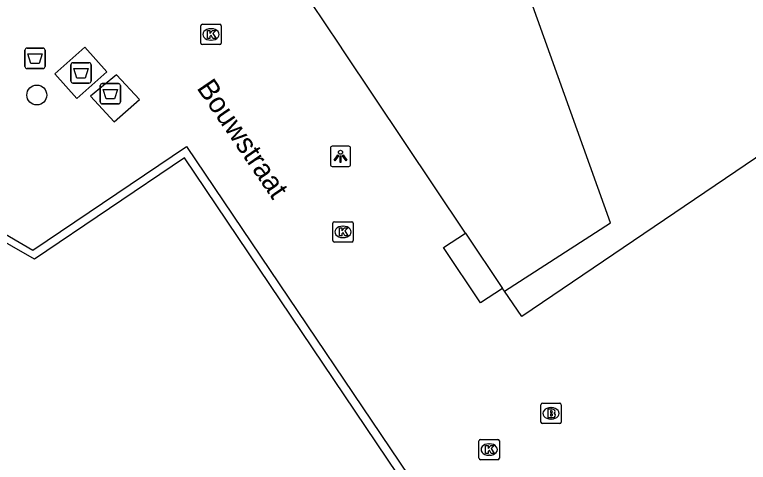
# Model space of a CAD drawing. Extents: x 161087 to 161922, y 382574 to 383873.
# Drawn here: x 161601.28 to 161637.33, y 382943.67 to 382965.65 of the extents above; entities that cross this region are included whole.
import ezdxf

# ---------------------------------------------------------------- set-up
doc = ezdxf.new("R2010")
doc.units = 0
for name, color, linetype in [('IMGEO_Afval_apart_plaats', 7, 'Continuous'), ('IMGEO_Afvalbak', 7, 'Continuous'), ('IMGEO_Boom', 7, 'Continuous'), ('IMGEO_Brandkraan', 7, 'Continuous'), ('IMGEO_Kolk', 7, 'Continuous'), ('IMGEO_Lichtpunt', 7, 'Continuous'), ('IMGEO_Openbare_ruimte_label', 7, 'Continuous'), ('IMGEO_Pand', 7, 'Continuous'), ('IMGEO_Voetpad_gesloten', 7, 'Continuous'), ('IMGEO_Voetpad_open', 7, 'Continuous')]:
    doc.layers.add(name, color=color, linetype=linetype)

msp = doc.modelspace()

# ---------------------------------------------------------------- linework, layer by layer
at = {"layer": 'IMGEO_Afval_apart_plaats'}
for p, q in [((161604.039, 382962.391), (161604.039, 382963.191)), ((161604.039, 382963.191), (161604.039, 382962.391)), ((161604.139, 382963.291), (161604.929, 382963.291)), ((161604.929, 382963.291), (161604.139, 382963.291)), ((161605.029, 382963.191), (161605.029, 382962.391)), ((161605.029, 382962.391), (161605.029, 382963.191)), ((161604.929, 382962.291), (161604.139, 382962.291)), ((161604.139, 382962.291), (161604.929, 382962.291)), ((161605.484, 382961.368), (161605.484, 382962.168)), ((161605.484, 382962.168), (161605.484, 382961.368)), ((161605.584, 382962.268), (161606.374, 382962.268)), ((161606.374, 382962.268), (161605.584, 382962.268)), ((161606.474, 382962.168), (161606.474, 382961.368)), ((161606.474, 382961.368), (161606.474, 382962.168)), ((161606.374, 382961.268), (161605.584, 382961.268)), ((161605.584, 382961.268), (161606.374, 382961.268))]:
    msp.add_line(p, q, dxfattribs=at)
for points in [[(161604.182, 382963.005), (161604.886, 382963.005), (161604.737, 382962.535), (161604.331, 382962.535), (161604.182, 382963.005)], [(161605.627, 382961.982), (161606.331, 382961.982), (161606.182, 382961.512), (161605.776, 382961.512), (161605.627, 382961.982)]]:
    msp.add_lwpolyline(points, dxfattribs=at)
for centre, start, end in [((161604.139, 382963.191), 90, 180), ((161604.139, 382963.191), 90, 180), ((161604.929, 382963.191), 0, 90), ((161604.929, 382963.191), 360, 90), ((161604.139, 382962.391), 180, 270), ((161604.139, 382962.391), 180, 270), ((161604.929, 382962.391), 270, 0), ((161604.929, 382962.391), 270, 0), ((161605.584, 382962.168), 90, 180), ((161605.584, 382962.168), 90, 180), ((161606.374, 382962.168), 0, 90), ((161606.374, 382962.168), 360, 90), ((161605.584, 382961.368), 180, 270), ((161605.584, 382961.368), 180, 270), ((161606.374, 382961.368), 270, 0), ((161606.374, 382961.368), 270, 0)]:
    msp.add_arc(centre, 0.1, start, end, dxfattribs=at)
at = {"layer": 'IMGEO_Afvalbak'}
for p, q in [((161601.784, 382963.106), (161601.784, 382963.906)), ((161601.784, 382963.906), (161601.784, 382963.106)), ((161601.884, 382964.006), (161602.674, 382964.006)), ((161602.674, 382964.006), (161601.884, 382964.006)), ((161602.774, 382963.906), (161602.774, 382963.106)), ((161602.774, 382963.106), (161602.774, 382963.906)), ((161602.674, 382963.006), (161601.884, 382963.006)), ((161601.884, 382963.006), (161602.674, 382963.006))]:
    msp.add_line(p, q, dxfattribs=at)
msp.add_lwpolyline([(161601.927, 382963.72), (161602.631, 382963.72), (161602.482, 382963.25), (161602.076, 382963.25), (161601.927, 382963.72)], dxfattribs=at)
for centre, start, end in [((161601.884, 382963.906), 90, 180), ((161601.884, 382963.906), 90, 180), ((161602.674, 382963.906), 0, 90), ((161602.674, 382963.906), 360, 90), ((161601.884, 382963.106), 180, 270), ((161601.884, 382963.106), 180, 270), ((161602.674, 382963.106), 270, 0), ((161602.674, 382963.106), 270, 0)]:
    msp.add_arc(centre, 0.1, start, end, dxfattribs=at)
at = {"layer": 'IMGEO_Boom'}
msp.add_circle((161602.366, 382961.705), 0.489, dxfattribs=at)
at = {"layer": 'IMGEO_Brandkraan'}
for p, q in [((161627.213, 382946.575), (161628.065, 382946.575)), ((161627.138, 382945.649), (161627.138, 382946.501)), ((161627.626, 382946.355), (161627.651, 382946.355)), ((161628.139, 382946.501), (161628.139, 382945.649)), ((161628.065, 382945.575), (161627.213, 382945.575)), ((161627.649, 382945.795), (161627.624, 382945.795))]:
    msp.add_line(p, q, dxfattribs=at)
for points in [[(161627.213, 382946.575), (161628.065, 382946.575)], [(161627.138, 382945.649), (161627.138, 382946.501)], [(161627.486, 382946.275), (161627.486, 382945.875), (161627.699, 382945.875)], [(161627.717, 382946.275), (161627.486, 382946.275)], [(161628.139, 382946.501), (161628.139, 382945.649)], [(161627.665, 382946.194), (161627.611, 382946.194), (161627.611, 382946.118)], [(161627.611, 382946.118), (161627.664, 382946.118)], [(161627.673, 382946.042), (161627.611, 382946.042), (161627.611, 382945.961)], [(161627.611, 382945.961), (161627.673, 382945.961)], [(161628.065, 382945.575), (161627.213, 382945.575)]]:
    msp.add_lwpolyline(points, dxfattribs=at)
for centre, radius, start, end in [((161627.215, 382946.499), 0.0765, 91.552, 178.448), ((161627.215, 382946.499), 0.0765, 91.552, 178.448), ((161628.063, 382946.499), 0.0765, 1.552, 88.448), ((161628.063, 382946.499), 0.0765, 1.552, 88.448), ((161627.721, 382946.13), 0.145, 59.4692, 91.5367), ((161627.746, 382946.177), 0.0922, 285.5137, 58.1501), ((161627.666, 382946.156), 0.0379, 267.8285, 90.9355), ((161627.674, 382946.001), 0.0404, 269.8759, 90.5077), ((161627.705, 382946.126), 0.251, 268.6676, 293.5347), ((161627.751, 382945.985), 0.105, 301.3115, 78.989), ((161627.215, 382945.651), 0.0765, 181.552, 268.448), ((161627.215, 382945.651), 0.0765, 181.552, 268.448), ((161628.063, 382945.651), 0.0765, 271.552, 358.448), ((161628.063, 382945.651), 0.0765, 271.552, 358.448)]:
    msp.add_arc(centre, radius, start, end, dxfattribs=at)
for centre, major_axis, ratio, start_param, end_param in [((161627.625, 382946.075), (-0.387, 0.002), 0.722429, 4.712389, 7.853982), ((161627.65, 382946.075), (-0.39, 0.002), 0.717154, 1.570796, 4.712389)]:
    msp.add_ellipse(centre, major_axis=major_axis, ratio=ratio, start_param=start_param, end_param=end_param, dxfattribs=at)
at = {"layer": 'IMGEO_Kolk'}
for p, q in [((161610.427, 382964.254), (161610.427, 382965.106)), ((161610.502, 382965.18), (161611.354, 382965.18)), ((161611.428, 382965.106), (161611.428, 382964.254)), ((161610.915, 382964.96), (161610.94, 382964.96)), ((161610.938, 382964.4), (161610.913, 382964.4)), ((161611.354, 382964.18), (161610.502, 382964.18)), ((161616.912, 382954.559), (161616.912, 382955.411)), ((161616.987, 382955.485), (161617.839, 382955.485)), ((161617.4, 382955.265), (161617.425, 382955.265)), ((161617.913, 382955.411), (161617.913, 382954.559)), ((161617.423, 382954.705), (161617.398, 382954.705)), ((161617.839, 382954.485), (161616.987, 382954.485)), ((161624.171, 382944.799), (161625.023, 382944.799)), ((161624.096, 382943.873), (161624.096, 382944.725)), ((161624.584, 382944.579), (161624.609, 382944.579)), ((161625.097, 382944.725), (161625.097, 382943.873)), ((161625.023, 382943.799), (161624.171, 382943.799)), ((161624.607, 382944.019), (161624.582, 382944.019))]:
    msp.add_line(p, q, dxfattribs=at)
for points in [[(161610.427, 382964.254), (161610.427, 382965.106)], [(161610.502, 382965.18), (161611.354, 382965.18)], [(161611.428, 382965.106), (161611.428, 382964.254)], [(161610.748, 382964.88), (161610.871, 382964.88), (161610.871, 382964.729), (161611.001, 382964.88), (161611.165, 382964.88), (161611.019, 382964.729), (161611.172, 382964.48), (161611.02, 382964.48), (161610.935, 382964.644), (161610.871, 382964.577), (161610.871, 382964.48), (161610.748, 382964.48), (161610.748, 382964.88)], [(161611.354, 382964.18), (161610.502, 382964.18)], [(161616.912, 382954.559), (161616.912, 382955.411)], [(161616.987, 382955.485), (161617.839, 382955.485)], [(161617.913, 382955.411), (161617.913, 382954.559)], [(161617.233, 382955.185), (161617.356, 382955.185), (161617.356, 382955.034), (161617.486, 382955.185), (161617.65, 382955.185), (161617.504, 382955.034), (161617.657, 382954.785), (161617.505, 382954.785), (161617.42, 382954.949), (161617.356, 382954.882), (161617.356, 382954.785), (161617.233, 382954.785), (161617.233, 382955.185)], [(161617.839, 382954.485), (161616.987, 382954.485)], [(161624.171, 382944.799), (161625.023, 382944.799)], [(161624.096, 382943.873), (161624.096, 382944.725)], [(161624.417, 382944.499), (161624.54, 382944.499), (161624.54, 382944.348), (161624.67, 382944.499), (161624.834, 382944.499), (161624.688, 382944.348), (161624.841, 382944.099), (161624.689, 382944.099), (161624.604, 382944.263), (161624.54, 382944.196), (161624.54, 382944.099), (161624.417, 382944.099), (161624.417, 382944.499)], [(161625.097, 382944.725), (161625.097, 382943.873)], [(161625.023, 382943.799), (161624.171, 382943.799)]]:
    msp.add_lwpolyline(points, dxfattribs=at)
for centre, start, end in [((161610.504, 382965.104), 91.552, 178.448), ((161610.504, 382965.104), 91.552, 178.448), ((161611.352, 382965.104), 1.552, 88.448), ((161611.352, 382965.104), 1.552, 88.448), ((161610.504, 382964.256), 181.552, 268.448), ((161610.504, 382964.256), 181.552, 268.448), ((161611.352, 382964.256), 271.552, 358.448), ((161611.352, 382964.256), 271.552, 358.448), ((161616.989, 382955.409), 91.552, 178.448), ((161616.989, 382955.409), 91.552, 178.448), ((161617.837, 382955.409), 1.552, 88.448), ((161617.837, 382955.409), 1.552, 88.448), ((161616.989, 382954.561), 181.552, 268.448), ((161616.989, 382954.561), 181.552, 268.448), ((161617.837, 382954.561), 271.552, 358.448), ((161617.837, 382954.561), 271.552, 358.448), ((161624.173, 382944.723), 91.552, 178.448), ((161624.173, 382944.723), 91.552, 178.448), ((161625.021, 382944.723), 1.552, 88.448), ((161625.021, 382944.723), 1.552, 88.448), ((161624.173, 382943.875), 181.552, 268.448), ((161624.173, 382943.875), 181.552, 268.448), ((161625.021, 382943.875), 271.552, 358.448), ((161625.021, 382943.875), 271.552, 358.448)]:
    msp.add_arc(centre, 0.0765, start, end, dxfattribs=at)
for centre, major_axis, ratio, start_param, end_param in [((161610.914, 382964.68), (-0.387, 0.002), 0.722429, 4.712389, 7.853982), ((161610.939, 382964.68), (-0.39, 0.002), 0.717154, 1.570796, 4.712389), ((161617.399, 382954.985), (-0.387, 0.002), 0.722429, 4.712389, 7.853982), ((161617.424, 382954.985), (-0.39, 0.002), 0.717154, 1.570796, 4.712389), ((161624.583, 382944.299), (-0.387, 0.002), 0.722429, 4.712389, 7.853982), ((161624.608, 382944.299), (-0.39, 0.002), 0.717154, 1.570796, 4.712389)]:
    msp.add_ellipse(centre, major_axis=major_axis, ratio=ratio, start_param=start_param, end_param=end_param, dxfattribs=at)
at = {"layer": 'IMGEO_Lichtpunt'}
for p, q in [((161616.791, 382959.098), (161616.791, 382958.291)), ((161616.791, 382959.098), (161616.791, 382958.291)), ((161617.693, 382959.193), (161616.885, 382959.193)), ((161617.693, 382959.193), (161616.885, 382959.193)), ((161617.787, 382958.291), (161617.787, 382959.098)), ((161617.787, 382958.291), (161617.787, 382959.098)), ((161616.885, 382958.197), (161617.693, 382958.197)), ((161616.885, 382958.197), (161617.693, 382958.197))]:
    msp.add_line(p, q, dxfattribs=at)
for points in [[(161617.165, 382958.762), (161617.204, 382958.734), (161617.016, 382958.472), (161616.978, 382958.499), (161617.165, 382958.762)], [(161617.267, 382958.714), (161617.314, 382958.714), (161617.314, 382958.392), (161617.267, 382958.392), (161617.267, 382958.714)], [(161617.377, 382958.734), (161617.415, 382958.761), (161617.602, 382958.499), (161617.563, 382958.471), (161617.377, 382958.734)]]:
    msp.add_lwpolyline(points, dxfattribs=at)
msp.add_circle((161617.29, 382958.896), 0.0994, dxfattribs=at)
for centre, start, end in [((161616.885, 382959.098), 90, 180), ((161616.885, 382959.098), 90, 180), ((161617.693, 382959.098), 0, 90), ((161617.693, 382959.098), 0, 90), ((161616.885, 382958.291), 180, 270), ((161616.885, 382958.291), 180, 270), ((161617.693, 382958.291), 270, 0), ((161617.693, 382958.291), 270, 360)]:
    msp.add_arc(centre, 0.0946, start, end, dxfattribs=at)
at = {"layer": 'IMGEO_Pand'}
for points in [[(161625.343, 382952.069), (161630.565, 382955.43), (161625.027, 382970.875), (161631.264, 382974.476), (161635.222, 382976.778), (161636.89, 382977.546), (161639.557, 382970.577)], [(161623.432, 382954.925), (161617.437, 382963.875), (161617.249, 382964.155), (161612.319, 382971.509)], [(161655.439, 382954.633), (161643.006, 382949.054), (161638.697, 382959.289), (161626.193, 382950.825), (161625.343, 382952.069)], [(161591.673, 382932.638), (161601.036, 382920.562), (161605.233, 382923.818), (161604.439, 382924.844), (161623.254, 382938.407), (161609.618, 382958.613), (161602.246, 382953.638), (161598.78, 382955.626), (161589.629, 382948.571)], [(161623.432, 382954.925), (161625.248, 382952.208)], [(161625.343, 382952.069), (161625.248, 382952.208)]]:
    msp.add_lwpolyline(points, dxfattribs=at)
at = {"layer": 'IMGEO_Voetpad_gesloten'}
for points in [[(161605.809, 382962.839), (161604.729, 382964.051), (161603.259, 382962.743), (161604.34, 382961.53), (161605.809, 382962.839)], [(161606.289, 382962.698), (161605.01, 382961.651), (161606.173, 382960.392), (161607.413, 382961.477), (161606.289, 382962.698)]]:
    msp.add_lwpolyline(points, dxfattribs=at)
at = {"layer": 'IMGEO_Voetpad_open'}
for points in [[(161589.365, 382948.884), (161598.708, 382956.104), (161602.176, 382954.091), (161609.726, 382959.172), (161623.818, 382938.295), (161616.858, 382933.297)], [(161625.248, 382952.208), (161624.17, 382951.503), (161622.355, 382954.213), (161623.432, 382954.925)]]:
    msp.add_lwpolyline(points, dxfattribs=at)

# ---------------------------------------------------------------- texts
at = {"layer": 'IMGEO_Openbare_ruimte_label'}
msp.add_text('Bouwstraat', height=1, rotation=304.3256, dxfattribs=at).set_placement((161610.198, 382962.049))

doc.saveas('drawing.dxf')
